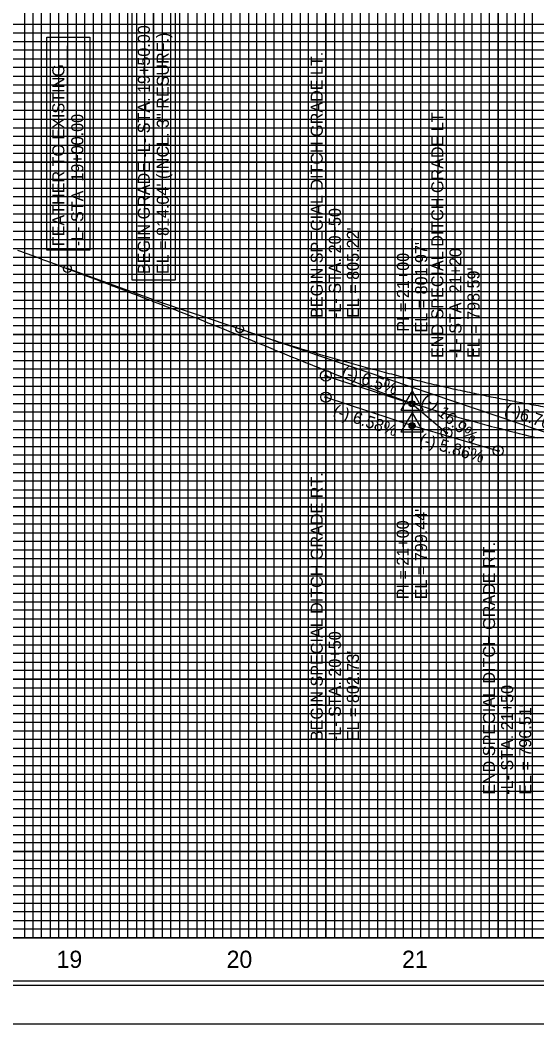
# Model space of a CAD drawing. Extents: x 573566 to 575250, y -53414 to -52314.
# Drawn here: x 573956 to 574256, y -53414 to -52832 of the extents above; entities that cross this region are included whole.
import ezdxf

# ---------------------------------------------------------------- set-up
doc = ezdxf.new("R2010")
doc.units = 0
for name, color, linetype in [('Exist Vertical Profile Ground Line', 7, 'Continuous'), ('Exist Vertical Profile Horizontal Axis Label Major', 7, 'Continuous'), ('Prop Grid Mask', 7, 'Continuous'), ('Prop PFL VPI Symbol CELL', 7, 'Continuous'), ('Prop Vertical Profile Curve Label', 7, 'Continuous'), ('Prop Vertical Profile Ditch Grade Left', 7, 'Continuous'), ('Prop Vertical Profile Ditch Grade Left Label', 7, 'Continuous'), ('Prop Vertical Profile Ditch Grade Right', 7, 'Continuous'), ('Prop Vertical Profile Ditch Grade Right Label', 7, 'Continuous'), ('Prop Vertical Profile Grade', 7, 'Continuous'), ('Prop Vertical Profile Grade Label', 7, 'Continuous'), ('Prop VPI Ditch Grade Left Label', 7, 'Continuous'), ('Prop VPI Ditch Grade Right Label', 7, 'Continuous'), ('Prop VPI Label', 7, 'Continuous'), ('Sheet Cutting Line CELL', 7, 'Continuous'), ('Sheet DOT Grid CELL', 7, 'Continuous'), ('Sheet Layout Profile Border', 7, 'Continuous'), ('Sheet Plot Border Inside CELL', 7, 'Continuous'), ('Sheet Plot Border Outside CELL', 7, 'Continuous'), ('Sheet Profile CELL', 7, 'Continuous'), ('Sheet Profile Grid Major CELL', 7, 'Continuous'), ('Sheet Profile Grid Middle CELL', 7, 'Continuous'), ('Sheet Profile Grid Minor CELL', 7, 'Continuous')]:
    doc.layers.add(name, color=color, linetype=linetype)

msp = doc.modelspace()

# ---------------------------------------------------------------- linework, layer by layer
at = {"layer": 'Exist Vertical Profile Ground Line'}
for points in [[(573954.31, -52965.01), (573956.73, -52965.9), (573957.01, -52966), (573959.71, -52967), (573962.4, -52968), (573965.1, -52969.01), (573967.8, -52970.01), (573968.88, -52970.42), (573970.49, -52971.02), (573973.19, -52972.03), (573975.89, -52973.04), (573978.58, -52974.05), (573979.34, -52974.34), (573979.66, -52974.46), (573981.28, -52975.06), (573983.98, -52976.07), (573986.67, -52977.09), (573989.37, -52978.1), (573992.07, -52979.12), (573994.76, -52980.14), (573997.46, -52981.16), (574000.16, -52982.18), (574002.85, -52983.2), (574005.55, -52984.23), (574008.25, -52985.26), (574008.94, -52985.53), (574009.34, -52985.68), (574009.69, -52985.81), (574010.94, -52986.29), (574013.64, -52987.32), (574016.34, -52988.34), (574019.03, -52989.37), (574021.73, -52990.4), (574024.43, -52991.44), (574027.12, -52992.47), (574029.82, -52993.51), (574032.51, -52994.55), (574032.54, -52994.56), (574033.19, -52994.82), (574035.21, -52995.59), (574037.91, -52996.63), (574040.6, -52997.66), (574043.3, -52998.7), (574046, -52999.74)], [(574046, -52999.74), (574048.69, -53000.79), (574051.39, -53001.83), (574054.09, -53002.88), (574055.85, -53003.57), (574056.2, -53003.71), (574056.78, -53003.94), (574059.48, -53005), (574059.87, -53005.16), (574062.18, -53006.08), (574064.87, -53007.16), (574067.57, -53008.25), (574070.27, -53009.33), (574072.96, -53010.42), (574075.66, -53011.5), (574078.36, -53012.59), (574081.05, -53013.68), (574083.75, -53014.77), (574084.37, -53015.02), (574085.5, -53015.48), (574086.45, -53015.87), (574086.71, -53015.98), (574089.14, -53016.97), (574091.84, -53018.07), (574094.54, -53019.17), (574097.23, -53020.27), (574099.93, -53021.37), (574102.63, -53022.47), (574105.32, -53023.58), (574108.02, -53024.68), (574110.72, -53025.79), (574113.41, -53026.89), (574113.96, -53027.12), (574116.11, -53028), (574116.44, -53028.13), (574118.81, -53029.08), (574121.5, -53030.15), (574124.2, -53031.23), (574126.89, -53032.31), (574129.59, -53033.39), (574132.29, -53034.47), (574134.98, -53035.55), (574137.68, -53036.62), (574138.14, -53036.81), (574140.38, -53037.73), (574140.58, -53037.81), (574143.07, -53038.78), (574145.77, -53039.84), (574148.47, -53040.89), (574151.16, -53041.94), (574153.86, -53042.99), (574156.56, -53044.05), (574159.25, -53045.1), (574161.95, -53046.15), (574162.54, -53046.38), (574164.65, -53047.19), (574165.14, -53047.38), (574167.34, -53048.17), (574170.04, -53049.15), (574172.74, -53050.12), (574175.43, -53051.09), (574178.13, -53052.07), (574179.92, -53052.71), (574180.83, -53053.02), (574182.69, -53053.65), (574183.52, -53053.91), (574186.22, -53054.75), (574188.92, -53055.59), (574191.61, -53056.43), (574194.31, -53057.27), (574197.01, -53058.11), (574199.7, -53058.95), (574202.4, -53059.78), (574204.72, -53060.51), (574205.1, -53060.61), (574206.94, -53061.13), (574207.79, -53061.37), (574210.49, -53062.11), (574213.19, -53062.86), (574215.88, -53063.6), (574218.58, -53064.35), (574221.28, -53065.09), (574223.97, -53065.84), (574226.67, -53066.58), (574228.95, -53067.21), (574229.36, -53067.3), (574231.09, -53067.71), (574232.06, -53067.95), (574234.76, -53068.63), (574237.45, -53069.32), (574240.15, -53070), (574242.85, -53070.68), (574245.54, -53071.36), (574248.24, -53072.04), (574250.94, -53072.72), (574253.03, -53073.25), (574253.63, -53073.39), (574254.52, -53073.59), (574256.33, -53073.95)]]:
    msp.add_lwpolyline(points, dxfattribs=at)
at = {"layer": 'Prop Grid Mask'}
for points in [[(574045.88, -52982.52), (574020.84, -52982.52), (574020.84, -52813.49), (574045.88, -52813.49)], [(573996.36, -52965.03), (573971.32, -52965.03), (573971.32, -52841.49), (573996.36, -52841.49)]]:
    msp.add_lwpolyline(points, close=True, dxfattribs=at)
at = {"layer": 'Prop PFL VPI Symbol CELL'}
for p, q in [((574183.3, -53046.72), (574176.85, -53057.92)), ((574183.3, -53046.72), (574189.8, -53057.92)), ((574176.85, -53057.92), (574189.8, -53057.92))]:
    msp.add_line(p, q, dxfattribs=at)
for radius in [1.75, 1.2]:
    msp.add_circle((574183.31, -53054.2), radius, dxfattribs=at)
at = {"layer": 'Prop Vertical Profile Curve Label'}
for centre in [(573983.31, -52975.76), (574083.31, -53010.76)]:
    msp.add_circle(centre, 2.25, dxfattribs=at)
at = {"layer": 'Prop Vertical Profile Ditch Grade Left'}
msp.add_lwpolyline([(574133.31, -53037.95), (574183.31, -53054.2), (574203.31, -53071.1)], dxfattribs=at)
at = {"layer": 'Prop Vertical Profile Ditch Grade Right'}
msp.add_lwpolyline([(574133.31, -53050.4), (574183.31, -53066.85), (574233.31, -53081.5)], dxfattribs=at)
at = {"layer": 'Prop Vertical Profile Ditch Grade Right Label'}
for p, q in [((574133.31, -53050.4), (574133.31, -53250.4)), ((574183.3, -53059.37), (574176.85, -53070.57)), ((574183.3, -53059.37), (574189.8, -53070.57)), ((574176.85, -53070.57), (574189.8, -53070.57)), ((574183.31, -53168.75), (574183.31, -53066.85)), ((574233.31, -53081.5), (574233.31, -53281.5))]:
    msp.add_line(p, q, dxfattribs=at)
for centre, radius in [((574133.31, -53050.4), 2.97), ((574183.31, -53066.85), 1.75), ((574183.31, -53066.85), 1.2), ((574233.31, -53081.5), 2.97)]:
    msp.add_circle(centre, radius, dxfattribs=at)
at = {"layer": 'Prop Vertical Profile Grade'}
for q in [(573983.31, -52975.76), (574083.31, -53010.76)]:
    msp.add_line((574033.31, -52993.85), q, dxfattribs=at)
msp.add_spline([(574083.31, -53010.76), (574094.31, -53014.42), (574105.31, -53017.97), (574116.31, -53021.41), (574127.31, -53024.73), (574138.31, -53027.94), (574149.31, -53031.03), (574160.31, -53034.02), (574171.31, -53036.89), (574182.31, -53039.64), (574193.31, -53042.29), (574204.31, -53044.82), (574215.31, -53047.23), (574226.31, -53049.53), (574237.31, -53051.72), (574248.31, -53053.8), (574259.31, -53055.76), (574270.31, -53057.61), (574281.31, -53059.35), (574292.31, -53060.97), (574303.31, -53062.48), (574314.31, -53063.88), (574325.31, -53065.16), (574336.31, -53066.33), (574347.31, -53067.38), (574358.31, -53068.33), (574369.31, -53069.16), (574380.31, -53069.87), (574391.31, -53070.47), (574402.31, -53070.96), (574413.31, -53071.34), (574424.31, -53071.6), (574435.31, -53071.75), (574446.31, -53071.79), (574457.31, -53071.71), (574468.31, -53071.52), (574479.31, -53071.21), (574490.31, -53070.79), (574501.31, -53070.26), (574512.31, -53069.62), (574523.31, -53068.86), (574534.31, -53067.99), (574545.31, -53067.01), (574556.31, -53065.91), (574567.31, -53064.7), (574578.31, -53063.37), (574589.31, -53061.93), (574600.31, -53060.38), (574611.31, -53058.72), (574622.31, -53056.94), (574633.31, -53055.05)], degree=3, dxfattribs=at)
at = {"layer": 'Prop VPI Ditch Grade Left Label'}
for p, q in [((574133.31, -53037.95), (574133.31, -52837.95)), ((574203.31, -53071.1), (574203.31, -52871.1)), ((574183.31, -53054.2), (574183.31, -52952.3))]:
    msp.add_line(p, q, dxfattribs=at)
for centre, radius in [((574133.31, -53037.95), 3.15), ((574133.31, -53037.95), 0.5), ((574183.31, -53054.2), 0.5), ((574203.31, -53071.1), 3.15), ((574203.31, -53071.1), 0.5)]:
    msp.add_circle(centre, radius, dxfattribs=at)
at = {"layer": 'Prop VPI Ditch Grade Right Label'}
for centre in [(574133.31, -53050.4), (574183.31, -53066.85), (574233.31, -53081.5)]:
    msp.add_circle(centre, 0.5, dxfattribs=at)
at = {"layer": 'Prop VPI Label'}
for p, q in [((574033.31, -52993.85), (574033.31, -52817.13)), ((573983.31, -52975.76), (573983.31, -52846.48)), ((574083.31, -53010.76), (574355.7, -53102.87))]:
    msp.add_line(p, q, dxfattribs=at)
at = {"layer": 'Sheet Cutting Line CELL'}
msp.add_line((573566.31, -53414.05), (575250.31, -53414.05), dxfattribs=at)
at = {"layer": 'Sheet DOT Grid CELL'}
for p, q in [((573983.31, -52339.05), (573983.31, -53364.05)), ((574033.31, -52339.05), (574033.31, -53364.05)), ((574083.31, -52339.05), (574083.31, -53364.05)), ((574133.31, -52339.05), (574133.31, -53364.05)), ((574183.31, -52339.05), (574183.31, -53364.05)), ((574233.31, -52339.05), (574233.31, -53364.05)), ((573733.31, -52864.05), (575233.31, -52864.05)), ((573733.31, -52914.05), (575233.31, -52914.05)), ((573733.31, -52964.05), (575233.31, -52964.05)), ((573733.31, -53014.05), (575233.31, -53014.05)), ((573733.31, -53064.05), (575233.31, -53064.05)), ((573733.31, -53114.05), (575233.31, -53114.05)), ((573733.31, -53164.05), (575233.31, -53164.05)), ((573733.31, -53214.05), (575233.31, -53214.05)), ((573733.31, -53264.05), (575233.31, -53264.05)), ((573733.31, -53314.05), (575233.31, -53314.05))]:
    msp.add_line(p, q, dxfattribs=at)
at = {"layer": 'Sheet Layout Profile Border'}
msp.add_lwpolyline([(573783.31, -52339.05), (573783.31, -53364.05), (575183.31, -53364.05), (575183.31, -52476.6), (575033.26, -52476.6), (575033.26, -52339.05)], close=True, dxfattribs=at)
at = {"layer": 'Sheet Plot Border Inside CELL'}
msp.add_lwpolyline([(575245.81, -52336.5), (573579.31, -52336.5), (573579.31, -53391.6), (575245.81, -53391.6)], close=True, dxfattribs=at)
at = {"layer": 'Sheet Plot Border Outside CELL'}
msp.add_lwpolyline([(575250.31, -52314.05), (573566.31, -52314.05), (573566.31, -53414.05), (575250.31, -53414.05)], close=True, dxfattribs=at)
at = {"layer": 'Sheet Profile CELL'}
msp.add_line((575233.31, -53364.05), (573733.31, -53364.05), dxfattribs=at)
msp.add_lwpolyline([(575233.31, -52339.05), (573733.31, -52339.05), (573733.31, -53389.05), (575233.31, -53389.05)], close=True, dxfattribs=at)
at = {"layer": 'Sheet Profile Grid Major CELL'}
for points in [[(573983.31, -52339.05), (573983.31, -53364.05), (574033.31, -53364.05), (574033.31, -52339.05)], [(574083.31, -52339.05), (574083.31, -53364.05), (574133.31, -53364.05), (574133.31, -52339.05)], [(574183.31, -52339.05), (574183.31, -53364.05), (574233.31, -53364.05), (574233.31, -52339.05)], [(575233.31, -52914.05), (573733.31, -52914.05), (573733.31, -52864.05), (575233.31, -52864.05)], [(575233.31, -53014.05), (573733.31, -53014.05), (573733.31, -52964.05), (575233.31, -52964.05)], [(575233.31, -53114.05), (573733.31, -53114.05), (573733.31, -53064.05), (575233.31, -53064.05)], [(575233.31, -53214.05), (573733.31, -53214.05), (573733.31, -53164.05), (575233.31, -53164.05)], [(575233.31, -53314.05), (573733.31, -53314.05), (573733.31, -53264.05), (575233.31, -53264.05)]]:
    msp.add_lwpolyline(points, dxfattribs=at)
at = {"layer": 'Sheet Profile Grid Middle CELL'}
for points in [[(573958.31, -52339.05), (573958.31, -53364.05), (574008.31, -53364.05), (574008.31, -52339.05)], [(574058.31, -52339.05), (574058.31, -53364.05), (574108.31, -53364.05), (574108.31, -52339.05)], [(574158.31, -52339.05), (574158.31, -53364.05), (574208.31, -53364.05), (574208.31, -52339.05)], [(575233.31, -52839.05), (573733.31, -52839.05), (573733.31, -52889.05), (575233.31, -52889.05)], [(575233.31, -52939.05), (573733.31, -52939.05), (573733.31, -52989.05), (575233.31, -52989.05)], [(575233.31, -53039.05), (573733.31, -53039.05), (573733.31, -53089.05), (575233.31, -53089.05)], [(575233.31, -53139.05), (573733.31, -53139.05), (573733.31, -53189.05), (575233.31, -53189.05)], [(575233.31, -53239.05), (573733.31, -53239.05), (573733.31, -53289.05), (575233.31, -53289.05)], [(575233.31, -53339.05), (573733.31, -53339.05)]]:
    msp.add_lwpolyline(points, dxfattribs=at)
at = {"layer": 'Sheet Profile Grid Minor CELL'}
for points in [[(573963.31, -52339.05), (573963.31, -53364.05), (573968.31, -53364.05), (573968.31, -52339.05)], [(573973.31, -52339.05), (573973.31, -53364.05), (573978.31, -53364.05), (573978.31, -52339.05)], [(573988.31, -52339.05), (573988.31, -53364.05), (573993.31, -53364.05), (573993.31, -52339.05)], [(573998.31, -52339.05), (573998.31, -53364.05), (574003.31, -53364.05), (574003.31, -52339.05)], [(574013.31, -52339.05), (574013.31, -53364.05), (574018.31, -53364.05), (574018.31, -52339.05)], [(574023.31, -52339.05), (574023.31, -53364.05), (574028.31, -53364.05), (574028.31, -52339.05)], [(574038.31, -52339.05), (574038.31, -53364.05), (574043.31, -53364.05), (574043.31, -52339.05)], [(574048.31, -52339.05), (574048.31, -53364.05), (574053.31, -53364.05), (574053.31, -52339.05)], [(574063.31, -52339.05), (574063.31, -53364.05), (574068.31, -53364.05), (574068.31, -52339.05)], [(574073.31, -52339.05), (574073.31, -53364.05), (574078.31, -53364.05), (574078.31, -52339.05)], [(574088.31, -52339.05), (574088.31, -53364.05), (574093.31, -53364.05), (574093.31, -52339.05)], [(574098.31, -52339.05), (574098.31, -53364.05), (574103.31, -53364.05), (574103.31, -52339.05)], [(574113.31, -52339.05), (574113.31, -53364.05), (574128.31, -53364.05), (574128.31, -52339.05)], [(574118.31, -52339.05), (574118.31, -53364.05), (574123.31, -53364.05), (574123.31, -52339.05)], [(574118.31, -52339.65), (574118.31, -53364.05), (574123.31, -53364.05), (574123.31, -52339.65)], [(574138.31, -52339.05), (574138.31, -53364.05), (574143.31, -53364.05), (574143.31, -52339.05)], [(574148.31, -52339.05), (574148.31, -53364.05), (574153.31, -53364.05), (574153.31, -52339.05)], [(574163.31, -52339.05), (574163.31, -53364.05), (574168.31, -53364.05), (574168.31, -52339.05)], [(574173.31, -52339.05), (574173.31, -53364.05), (574178.31, -53364.05), (574178.31, -52339.05)], [(574188.31, -52339.05), (574188.31, -53364.05), (574193.31, -53364.05), (574193.31, -52339.05)], [(574198.31, -52339.05), (574198.31, -53364.05), (574203.31, -53364.05), (574203.31, -52339.05)], [(574213.31, -52339.05), (574213.31, -53364.05), (574218.31, -53364.05), (574218.31, -52339.05)], [(574223.31, -52339.05), (574223.31, -53364.05), (574228.31, -53364.05), (574228.31, -52339.05)], [(574238.31, -52339.05), (574238.31, -53364.05), (574243.31, -53364.05), (574243.31, -52339.05)], [(574248.31, -52339.05), (574248.31, -53364.05), (574253.31, -53364.05), (574253.31, -52339.05)], [(575183.31, -52834.05), (573783.31, -52834.05), (573783.31, -52844.05), (575183.31, -52844.05)], [(575183.31, -52849.05), (573783.31, -52849.05), (573783.31, -52854.05), (575183.31, -52854.05)], [(575183.31, -52859.05), (573783.31, -52859.05)], [(573783.31, -52869.05), (575183.31, -52869.05)], [(575183.31, -52874.05), (573783.31, -52874.05), (573783.31, -52879.05), (575183.31, -52879.05)], [(575183.31, -52884.05), (573783.31, -52884.05), (573783.31, -52894.05), (575183.31, -52894.05)], [(575183.31, -52899.05), (573783.31, -52899.05), (573783.31, -52904.05), (575183.31, -52904.05)], [(575183.31, -52909.05), (573783.31, -52909.05), (573783.31, -52919.05), (575183.31, -52919.05)], [(575183.31, -52924.05), (573783.31, -52924.05), (573783.31, -52929.05), (575183.31, -52929.05)], [(575183.31, -52934.05), (573783.31, -52934.05), (573783.31, -52944.05), (575183.31, -52944.05)], [(575183.31, -52949.05), (573783.31, -52949.05), (573783.31, -52954.05), (575183.31, -52954.05)], [(575183.31, -52959.05), (573783.31, -52959.05), (573783.31, -52969.05), (575183.31, -52969.05)], [(575183.31, -52974.05), (573783.31, -52974.05), (573783.31, -52979.05), (575183.31, -52979.05)], [(575183.31, -52984.05), (573783.31, -52984.05), (573783.31, -52994.05), (575183.31, -52994.05)], [(575183.31, -52999.05), (573783.31, -52999.05), (573783.31, -53004.05), (575183.31, -53004.05)], [(575183.31, -53009.05), (573783.31, -53009.05), (573783.31, -53019.05), (575183.31, -53019.05)], [(575183.31, -53024.05), (573783.31, -53024.05), (573783.31, -53029.05), (575183.31, -53029.05)], [(575183.31, -53034.05), (573783.31, -53034.05), (573783.31, -53044.05), (575183.31, -53044.05)], [(575183.31, -53049.05), (573783.31, -53049.05), (573783.31, -53054.05), (575183.31, -53054.05)], [(575183.31, -53059.05), (573783.31, -53059.05), (573783.31, -53069.05), (575183.31, -53069.05)], [(575183.31, -53074.05), (573783.31, -53074.05), (573783.31, -53079.05), (575183.31, -53079.05)], [(575183.31, -53084.05), (573783.31, -53084.05), (573783.31, -53094.05), (575183.31, -53094.05)], [(575183.31, -53099.05), (573783.31, -53099.05), (573783.31, -53104.05), (575183.31, -53104.05)], [(575183.31, -53109.05), (573783.31, -53109.05), (573783.31, -53119.05), (575183.31, -53119.05)], [(575183.31, -53124.05), (573783.31, -53124.05), (573783.31, -53129.05), (575183.31, -53129.05)], [(575183.31, -53134.05), (573783.31, -53134.05), (573783.31, -53144.05), (575183.31, -53144.05)], [(575183.31, -53149.05), (573783.31, -53149.05), (573783.31, -53154.05), (575183.31, -53154.05)], [(575183.31, -53159.05), (573783.31, -53159.05)], [(573783.31, -53169.05), (575183.31, -53169.05)], [(575183.31, -53174.05), (573783.31, -53174.05), (573783.31, -53179.05), (575183.31, -53179.05)], [(575183.31, -53184.05), (573783.31, -53184.05)], [(573783.31, -53194.05), (575183.31, -53194.05)], [(575183.31, -53199.05), (573783.31, -53199.05), (573783.31, -53204.05), (575183.31, -53204.05)], [(575183.31, -53209.05), (573783.31, -53209.05), (573783.31, -53219.05), (575183.31, -53219.05)], [(575183.31, -53224.05), (573783.31, -53224.05), (573783.31, -53229.05), (575183.31, -53229.05)], [(575183.31, -53234.05), (573783.31, -53234.05), (573783.31, -53244.05), (575183.31, -53244.05)], [(575183.31, -53249.05), (573783.31, -53249.05), (573783.31, -53254.05), (575183.31, -53254.05)], [(575183.31, -53259.05), (573783.31, -53259.05), (573783.31, -53269.05), (575183.31, -53269.05)], [(575183.31, -53274.05), (573783.31, -53274.05), (573783.31, -53279.05), (575183.31, -53279.05)], [(575183.31, -53284.05), (573783.31, -53284.05), (573783.31, -53294.05), (575183.31, -53294.05)], [(575183.31, -53299.05), (573783.31, -53299.05), (573783.31, -53304.05), (575183.31, -53304.05)], [(575183.31, -53309.05), (573783.31, -53309.05), (573783.31, -53319.05), (575183.31, -53319.05)], [(575183.31, -53324.05), (573783.31, -53324.05), (573783.31, -53329.05), (575183.31, -53329.05)], [(575183.31, -53334.05), (573783.31, -53334.05), (573783.31, -53344.05), (575183.31, -53344.05)], [(575183.31, -53349.05), (573783.31, -53349.05), (573783.31, -53354.05), (575183.31, -53354.05)], [(575183.31, -53359.05), (573783.31, -53359.05)]]:
    msp.add_lwpolyline(points, dxfattribs=at)

# ---------------------------------------------------------------- texts
at = {"layer": 'Exist Vertical Profile Horizontal Axis Label Major'}
for s, p in [('19', (573977.01, -53381.55)), ('20', (574075.69, -53381.55)), ('21', (574177.53, -53381.55))]:
    msp.add_text(s, height=10, dxfattribs=at).set_placement(p)
at = {"layer": 'Prop Vertical Profile Ditch Grade Left Label'}
for s, rotation, p in [('(-) 6.5%', 341.99584, (574141.85, -53038.73)), ('(-) 16.9%', 319.80219, (574188.49, -53052.51))]:
    msp.add_text(s, height=7, rotation=rotation, dxfattribs=at).set_placement(p)
at = {"layer": 'Prop Vertical Profile Ditch Grade Right Label'}
for s, rotation, p in [('(-) 6.58%', 341.78879, (574136.93, -53061.22)), ('(-) 5.86%', 343.66942, (574187.05, -53077.82))]:
    msp.add_text(s, height=7, rotation=rotation, dxfattribs=at).set_placement(p)
at = {"layer": 'Prop Vertical Profile Grade Label'}
msp.add_text('(-)6.7631%', height=7, rotation=341.31684, dxfattribs=at).set_placement((574236.38, -53060.26))
at = {"layer": 'Prop VPI Ditch Grade Left Label'}
for s, p in [('BEGIN SPECIAL DITCH GRADE LT.', (574131.5, -53004.39)), ('END SPECIAL DITCH GRADE LT.', (574201.5, -53027.62)), ('-L- STA. 20+50', (574142, -53004.39)), ("EL = 805.22'", (574152.5, -53004.39)), ("EL = 801.97'", (574192.12, -53012.86)), ('-L- STA. 21+20', (574212, -53027.62)), ('PI = 21+00', (574181.56, -53012.41)), ("EL = 798.59'", (574222.5, -53027.62))]:
    msp.add_text(s, height=7, rotation=90, dxfattribs=at).set_placement(p)
at = {"layer": 'Prop VPI Ditch Grade Right Label'}
for s, p in [('BEGIN SPECIAL DITCH GRADE RT.', (574131.5, -53249.98)), ("EL = 799.44'", (574192.03, -53167.66)), ('PI = 21+00', (574181.43, -53167.66)), ('END SPECIAL DITCH GRADE RT.', (574231.5, -53281.08)), ('-L- STA. 20+50', (574142, -53249.98)), ("EL = 802.73'", (574152.5, -53249.98)), ('-L- STA. 21+50', (574242, -53281.08)), ("EL = 796.51'", (574252.5, -53281.08))]:
    msp.add_text(s, height=7, rotation=90, dxfattribs=at).set_placement(p)
at = {"layer": 'Prop VPI Label'}
for s, p in [('BEGIN GRADE -L- STA. 19+50.00', (574031.14, -52978.93)), ('EL = 814.04\' (INCL. 3" RESURF.)', (574042.14, -52978.93)), ('FEATHER TO EXISTING', (573981.52, -52962.75)), ('-L- STA. 19+00.00', (573992.52, -52962.75))]:
    msp.add_text(s, height=7, rotation=90, dxfattribs=at).set_placement(p)

doc.saveas('drawing.dxf')
